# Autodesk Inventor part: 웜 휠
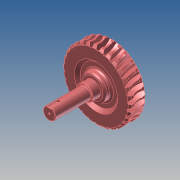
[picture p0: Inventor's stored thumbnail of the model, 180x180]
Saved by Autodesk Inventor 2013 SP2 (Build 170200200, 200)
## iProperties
Created: 2025-06
Part Number: 웜 휠
Material: Generic
Document SubType Name: Modeling
Designer: i
Density: 1 g/cm^3
Author: i
변환 표준: STEP AP214IS
전처리기: Build: 200, Release: 2013 SP2 Update 6 - Date: Thu 07/17/2014
전송 단위: 밀리미터
불확실성: 0.01
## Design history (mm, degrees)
node "웜 휠1"
body "Solid1"
node "기준1"
